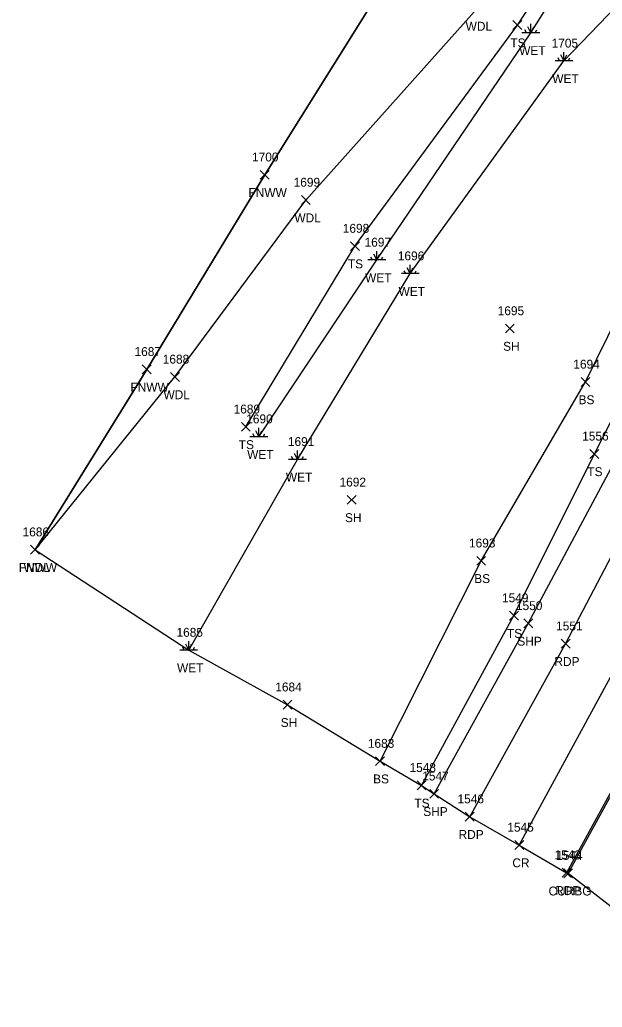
# Model space of a CAD drawing. Extents: x 1623612 to 1625808, y 621345 to 627748.
# Drawn here: x 1624324.5 to 1624455.5, y 625672.8 to 625894.9 of the extents above; entities that cross this region are included whole.
import ezdxf

# ---------------------------------------------------------------- set-up
doc = ezdxf.new("R2010")
doc.units = 0
for name, color, linetype in [('L_A', 7, 'Continuous'), ('L_I', 7, 'Continuous'), ('L_TIC', 7, 'Continuous'), ('LAWA', 7, 'Continuous'), ('LELB', 7, 'Continuous'), ('LFNC', 7, 'Continuous'), ('LSOGP', 7, 'Continuous'), ('LWET', 7, 'Continuous'), ('P_A', 7, 'Continuous'), ('P_I', 7, 'Continuous'), ('P_TIC', 7, 'Continuous'), ('PET', 7, 'Continuous'), ('PRC', 7, 'Continuous'), ('PSP', 7, 'Continuous'), ('R_A', 7, 'Continuous'), ('R_I', 7, 'Continuous'), ('R_TIC', 7, 'Continuous'), ('RC', 7, 'Continuous')]:
    doc.layers.add(name, color=color, linetype=linetype)

msp = doc.modelspace()

# ---------------------------------------------------------------- linework, layer by layer
at = {"layer": 'L_TIC'}
for points in [[(1624435.39, 625892.65), (1624437.39, 625894.65)], [(1624437.39, 625892.65), (1624435.39, 625894.65)], [(1624378.58, 625858.99), (1624380.58, 625860.99)], [(1624380.58, 625858.99), (1624378.58, 625860.99)], [(1624387.82, 625853.31), (1624389.82, 625855.31)], [(1624389.82, 625853.31), (1624387.82, 625855.31)], [(1624398.86, 625842.95), (1624400.86, 625844.95)], [(1624400.86, 625842.95), (1624398.86, 625844.95)], [(1624433.69, 625824.42), (1624435.69, 625826.42)], [(1624435.69, 625824.42), (1624433.69, 625826.42)], [(1624352.03, 625815.24), (1624354.03, 625817.24)], [(1624354.03, 625815.24), (1624352.03, 625817.24)], [(1624358.38, 625813.53), (1624360.38, 625815.53)], [(1624360.38, 625813.53), (1624358.38, 625815.53)], [(1624450.7, 625812.41), (1624452.7, 625814.41)], [(1624452.7, 625812.41), (1624450.7, 625814.41)], [(1624374.32, 625802.31), (1624376.32, 625804.31)], [(1624376.32, 625802.31), (1624374.32, 625804.31)], [(1624452.7, 625796.23), (1624454.7, 625798.23)], [(1624454.7, 625796.23), (1624452.7, 625798.23)], [(1624398.14, 625785.89), (1624400.14, 625787.89)], [(1624400.14, 625785.89), (1624398.14, 625787.89)], [(1624326.92, 625774.69), (1624328.92, 625776.69)], [(1624328.92, 625774.69), (1624326.92, 625776.69)], [(1624326.92, 625774.69), (1624328.92, 625776.69)], [(1624328.92, 625774.69), (1624326.92, 625776.69)], [(1624427.24, 625772.19), (1624429.24, 625774.19)], [(1624429.24, 625772.19), (1624427.24, 625774.19)], [(1624434.62, 625759.87), (1624436.62, 625761.87)], [(1624436.62, 625759.87), (1624434.62, 625761.87)], [(1624383.68, 625739.82), (1624385.68, 625741.82)], [(1624385.68, 625739.82), (1624383.68, 625741.82)], [(1624404.5, 625727.14), (1624406.5, 625729.14)], [(1624406.5, 625727.14), (1624404.5, 625729.14)], [(1624413.82, 625721.7), (1624415.82, 625723.7)], [(1624415.82, 625721.7), (1624413.82, 625723.7)]]:
    msp.add_lwpolyline(points, dxfattribs=at)
at = {"layer": 'LAWA'}
msp.add_lwpolyline([(1624327.92, 625775.69), (1624359.38, 625814.53), (1624388.82, 625854.31), (1624427.33, 625897.39), (1624446.74, 625934.23), (1624449.98, 625974.47)], dxfattribs=at)
at = {"layer": 'LELB'}
for points in [[(1624405.5, 625728.14), (1624428.24, 625773.19), (1624451.7, 625813.41), (1624479.3, 625869.39), (1624496.23, 625906.08), (1624514.91, 625948.11), (1624536.21, 625990.48), (1624546.45, 626029.66), (1624561.04, 626063.21), (1624576.65, 626110.9), (1624590.48, 626147.32), (1624609.26, 626181.73), (1624628.06, 626219.01), (1624648.51, 626267.43), (1624661.85, 626303.08), (1624661.36, 626343.87), (1624651.86, 626347.04), (1624650.32, 626353.64), (1624652.97, 626362.16), (1624638.4, 626383.22), (1624618.17, 626397.94), (1624604.09, 626415.44)], [(1624375.32, 625803.31), (1624399.86, 625843.95), (1624436.39, 625893.65), (1624461.77, 625932.24), (1624474.24, 625964.36), (1624492.43, 626012.44), (1624506.84, 626058.35), (1624517.83, 626084.66), (1624533.25, 626127.2), (1624547.8, 626166.97), (1624564.84, 626204.52), (1624581.23, 626246.76), (1624598.57, 626285.31), (1624600.66, 626320.03), (1624610.19, 626356.83), (1624599.69, 626375.7), (1624596.69, 626386.19), (1624590.38, 626400.67)], [(1624414.82, 625722.7), (1624435.62, 625760.87), (1624453.7, 625797.23), (1624474.13, 625837.17), (1624493.41, 625878.76), (1624511.69, 625916.21), (1624528.38, 625951.55), (1624544.66, 625990.22), (1624558.02, 626027.25), (1624569.94, 626061.58), (1624576.34, 626070.61), (1624593.27, 626109.93), (1624608.95, 626149.66), (1624624.61, 626188.43), (1624639.61, 626224.64), (1624652.78, 626258.96), (1624662.63, 626284.81), (1624668.95, 626309.14), (1624669.8, 626328.28), (1624669.98, 626343.79)]]:
    msp.add_lwpolyline(points, dxfattribs=at)
at = {"layer": 'LFNC'}
msp.add_lwpolyline([(1624327.92, 625775.69), (1624353.03, 625816.24), (1624379.58, 625859.99), (1624410.91, 625910.13), (1624427.61, 625937.89)], dxfattribs=at)
at = {"layer": 'LSOGP'}
msp.add_lwpolyline([(1624410.91, 625910.13), (1624379.58, 625859.99), (1624353.03, 625816.24), (1624327.92, 625775.69), (1624362.47, 625753.11), (1624384.68, 625740.82), (1624405.5, 625728.14), (1624414.82, 625722.7), (1624417.68, 625720.8), (1624425.67, 625715.65), (1624436.82, 625709.28), (1624447.42, 625703.06), (1624447.8, 625702.94), (1624459.81, 625693.66), (1624460.07, 625693.53), (1624471.41, 625686.57), (1624481.98, 625680.63), (1624490.77, 625675.48), (1624492.6, 625674.09), (1624515.98, 625657.65)], dxfattribs=at)
at = {"layer": 'LWET'}
for p, q in [((1624441.42, 625891.91), (1624437.42, 625891.91)), ((1624438.42, 625891.91), (1624438.08, 625892.57)), ((1624439.42, 625891.91), (1624438.75, 625893.24)), ((1624439.42, 625891.91), (1624439.42, 625893.91)), ((1624439.42, 625891.91), (1624440.08, 625893.24)), ((1624440.42, 625891.91), (1624440.75, 625892.57)), ((1624446.85, 625885.6), (1624446.85, 625887.6)), ((1624448.85, 625885.6), (1624444.85, 625885.6)), ((1624445.85, 625885.6), (1624445.52, 625886.27)), ((1624446.85, 625885.6), (1624446.19, 625886.93)), ((1624446.85, 625885.6), (1624447.52, 625886.93)), ((1624447.85, 625885.6), (1624448.19, 625886.27)), ((1624406.77, 625840.83), (1624402.77, 625840.83)), ((1624403.77, 625840.83), (1624403.43, 625841.5)), ((1624404.77, 625840.83), (1624404.1, 625842.16)), ((1624404.77, 625840.83), (1624404.77, 625842.83)), ((1624404.77, 625840.83), (1624405.43, 625842.16)), ((1624405.77, 625840.83), (1624406.1, 625841.5)), ((1624412.3, 625837.76), (1624411.63, 625839.09)), ((1624412.3, 625837.76), (1624412.3, 625839.76)), ((1624412.3, 625837.76), (1624412.96, 625839.09)), ((1624414.3, 625837.76), (1624410.3, 625837.76)), ((1624411.3, 625837.76), (1624410.96, 625838.43)), ((1624413.3, 625837.76), (1624413.63, 625838.43)), ((1624378.24, 625801.1), (1624378.24, 625803.1)), ((1624380.24, 625801.1), (1624376.24, 625801.1)), ((1624377.24, 625801.1), (1624376.91, 625801.77)), ((1624378.24, 625801.1), (1624377.57, 625802.43)), ((1624378.24, 625801.1), (1624378.91, 625802.43)), ((1624379.24, 625801.1), (1624379.57, 625801.77)), ((1624385.95, 625796), (1624385.62, 625796.67)), ((1624386.95, 625796), (1624386.29, 625797.34)), ((1624386.95, 625796), (1624386.95, 625798)), ((1624386.95, 625796), (1624387.62, 625797.34)), ((1624387.95, 625796), (1624388.29, 625796.67)), ((1624388.95, 625796), (1624384.95, 625796)), ((1624362.47, 625753.11), (1624361.8, 625754.45)), ((1624362.47, 625753.11), (1624362.47, 625755.11)), ((1624362.47, 625753.11), (1624363.13, 625754.45)), ((1624364.47, 625753.11), (1624360.47, 625753.11)), ((1624361.47, 625753.11), (1624361.13, 625753.78)), ((1624363.47, 625753.11), (1624363.8, 625753.78))]:
    msp.add_line(p, q, dxfattribs=at)
for points in [[(1624378.24, 625801.1), (1624404.77, 625840.83), (1624439.42, 625891.91), (1624464.15, 625931.23), (1624475.9, 625962)], [(1624362.47, 625753.11), (1624386.95, 625796), (1624412.3, 625837.76), (1624446.85, 625885.6), (1624474.51, 625914.41), (1624486.36, 625910.16), (1624487.21, 625914.04), (1624468.66, 625928.53), (1624478.34, 625960.64)]]:
    msp.add_lwpolyline(points, dxfattribs=at)
at = {"layer": 'P_TIC'}
for points in [[(1624437.84, 625758.11), (1624439.84, 625760.11)], [(1624439.84, 625758.11), (1624437.84, 625760.11)], [(1624446.22, 625753.54), (1624448.22, 625755.54)], [(1624448.22, 625753.54), (1624446.22, 625755.54)], [(1624416.68, 625719.8), (1624418.68, 625721.8)], [(1624418.68, 625719.8), (1624416.68, 625721.8)], [(1624424.67, 625714.65), (1624426.67, 625716.65)], [(1624426.67, 625714.65), (1624424.67, 625716.65)], [(1624435.82, 625708.28), (1624437.82, 625710.28)], [(1624437.82, 625708.28), (1624435.82, 625710.28)], [(1624446.42, 625702.06), (1624448.42, 625704.06)], [(1624448.42, 625702.06), (1624446.42, 625704.06)]]:
    msp.add_lwpolyline(points, dxfattribs=at)
at = {"layer": 'PET'}
for points in [[(1624425.67, 625715.65), (1624447.22, 625754.54), (1624466.36, 625791.08), (1624487.12, 625831.75), (1624506.3, 625871.9), (1624524.08, 625910.61), (1624540.03, 625946.09), (1624556.56, 625984.64), (1624572.71, 626022.65), (1624589.71, 626064.03), (1624605.99, 626104.3), (1624622.34, 626144.13), (1624637.91, 626182.32), (1624652.97, 626219.87), (1624666.22, 626252.76), (1624676.12, 626279.69), (1624681.8, 626301.06), (1624682.54, 626327.48), (1624678.38, 626346.43)], [(1624700.76, 626272.27), (1624689.28, 626244.04), (1624672.95, 626203.67), (1624657.22, 626165.07), (1624639.97, 626122.42), (1624626.87, 626089.89), (1624609.23, 626047.25), (1624593.09, 626008.04), (1624578.04, 625971.53), (1624565.57, 625940.71), (1624555.47, 625915.78), (1624541.27, 625885.85), (1624534.37, 625871.9), (1624518.06, 625838.28), (1624503.61, 625808.5), (1624484.54, 625771.45), (1624465.59, 625736.05), (1624447.42, 625703.06)]]:
    msp.add_lwpolyline(points, dxfattribs=at)
at = {"layer": 'PRC'}
msp.add_lwpolyline([(1624436.82, 625709.28), (1624458.78, 625749.62), (1624477.65, 625785.2), (1624498.86, 625827.51), (1624517.91, 625866.07), (1624535.88, 625905.07), (1624552.01, 625941.13), (1624568.1, 625980.06), (1624584.2, 626018.31), (1624601.56, 626060.15), (1624617.86, 626100.59), (1624633.9, 626140.47), (1624649.73, 626177.64), (1624664.57, 626215.84), (1624677.89, 626248.35), (1624689.08, 626275.05), (1624700.91, 626304.1), (1624709.94, 626325.53), (1624717.47, 626344.65), (1624728.1, 626371.26)], dxfattribs=at)
at = {"layer": 'PSP'}
msp.add_lwpolyline([(1624417.68, 625720.8), (1624438.84, 625759.11), (1624458.11, 625795.15), (1624478.38, 625835.72), (1624497.98, 625876.28), (1624515.71, 625914.28), (1624531.6, 625950.04), (1624547.22, 625988.82), (1624563.29, 626026.94), (1624580.72, 626068.16), (1624597.18, 626108), (1624613.35, 626148.06), (1624629.33, 626186.41), (1624644.21, 626222.86), (1624657.67, 626256.77), (1624667.93, 626283.18), (1624675.15, 626305.88), (1624676.55, 626327.48), (1624673.72, 626344.86)], dxfattribs=at)
at = {"layer": 'R_TIC'}
for points in [[(1624446.8, 625701.94), (1624448.8, 625703.94)], [(1624448.8, 625701.94), (1624446.8, 625703.94)]]:
    msp.add_lwpolyline(points, dxfattribs=at)
at = {"layer": 'RC'}
msp.add_lwpolyline([(1624700.99, 626272.06), (1624689.6, 626244.03), (1624673.22, 626203.62), (1624657.61, 626165.02), (1624640.13, 626122.2), (1624627.02, 626089.91), (1624609.59, 626047.26), (1624593.5, 626007.85), (1624578.4, 625971.27), (1624565.79, 625940.64), (1624555.58, 625915.85), (1624541.27, 625885.85), (1624534.86, 625871.82), (1624518.48, 625838.05), (1624503.94, 625808.16), (1624484.9, 625771.28), (1624465.88, 625735.89), (1624447.8, 625702.94)], dxfattribs=at)

# ---------------------------------------------------------------- texts
at = {"layer": 'L_A'}
for s, p in [('WDL', (1624424.75, 625892.39)), ('TS', (1624434.8, 625888.65)), ('WET', (1624436.79, 625886.91)), ('WET', (1624444.23, 625880.6)), ('FNWW', (1624375.92, 625854.99)), ('WDL', (1624386.24, 625849.31)), ('TS', (1624398.27, 625838.95)), ('WET', (1624402.14, 625835.83)), ('WET', (1624409.67, 625832.76)), ('SH', (1624433.18, 625820.42)), ('FNWW', (1624349.38, 625811.24)), ('WDL', (1624356.8, 625809.53)), ('BS', (1624450.14, 625808.41)), ('TS', (1624373.73, 625798.31)), ('WET', (1624375.62, 625796.1)), ('TS', (1624452.11, 625792.23)), ('WET', (1624384.33, 625791)), ('SH', (1624397.63, 625781.89)), ('FNWW', (1624324.26, 625770.69)), ('WDL', (1624325.33, 625770.69)), ('BS', (1624426.68, 625768.19)), ('TS', (1624434.03, 625755.87)), ('WET', (1624359.85, 625748.11)), ('SH', (1624383.17, 625735.82)), ('BS', (1624403.94, 625723.14)), ('TS', (1624413.23, 625717.7))]:
    msp.add_text(s, height=2, dxfattribs=at).set_placement(p)
at = {"layer": 'L_I'}
for s, p in [('1705', (1624444.08, 625888.6)), ('1700', (1624376.72, 625862.99)), ('1699', (1624386.07, 625857.31)), ('1698', (1624397.12, 625846.95)), ('1697', (1624402.02, 625843.83)), ('1696', (1624409.5, 625840.76)), ('1695', (1624431.95, 625828.42)), ('1687', (1624350.29, 625819.24)), ('1688', (1624356.64, 625817.53)), ('1694', (1624448.96, 625816.41)), ('1689', (1624372.57, 625806.31)), ('1690', (1624375.41, 625804.1)), ('1691', (1624384.78, 625799)), ('1556', (1624450.95, 625800.23)), ('1692', (1624396.4, 625789.89)), ('1686', (1624325.12, 625778.69)), ('1686', (1624325.12, 625778.69)), ('1693', (1624425.5, 625776.19)), ('1549', (1624432.92, 625763.87)), ('1685', (1624359.73, 625756.11)), ('1684', (1624381.94, 625743.82)), ('1683', (1624402.76, 625731.14)), ('1548', (1624412.13, 625725.7))]:
    msp.add_text(s, height=2, dxfattribs=at).set_placement(p)
at = {"layer": 'P_A'}
for s, p in [('SHP', (1624436.37, 625754.11)), ('RDP', (1624444.71, 625749.54)), ('SHP', (1624415.22, 625715.8)), ('RDP', (1624423.16, 625710.65)), ('CR', (1624435.25, 625704.28)), ('RDP', (1624444.91, 625698.06))]:
    msp.add_text(s, height=2, dxfattribs=at).set_placement(p)
at = {"layer": 'P_I'}
for s, p in [('1550', (1624436.06, 625762.11)), ('1551', (1624445.09, 625757.54)), ('1547', (1624414.99, 625723.8)), ('1546', (1624422.92, 625718.65)), ('1545', (1624434.12, 625712.28)), ('1543', (1624444.73, 625706.06))]:
    msp.add_text(s, height=2, dxfattribs=at).set_placement(p)
at = {"layer": 'R_A'}
msp.add_text('CURBG', height=2, dxfattribs=at).set_placement((1624443.39, 625697.94))
at = {"layer": 'R_I'}
msp.add_text('1544', height=2, dxfattribs=at).set_placement((1624445.11, 625705.94))

doc.saveas('drawing.dxf')
